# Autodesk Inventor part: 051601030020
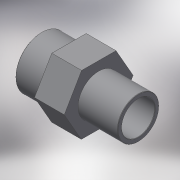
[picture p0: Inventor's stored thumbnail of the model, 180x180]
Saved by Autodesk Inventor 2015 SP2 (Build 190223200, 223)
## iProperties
Created: 2017-10
Part Number: 051601030020
Material: Generic
Description: PLASSON THR. REDUCING NIPPLE 3"-2" PVC
Document SubType Name: Modeling
Designer: KIM
Density: 1 g/cm^3
Appearance: Default
Author: KIM
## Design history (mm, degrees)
derived "051601.ipt"
feature "Solid1::051601.ipt"
tag "TaggingFeature1"
body "Solid1"
other parameters: "d0" = 83, "d13" = 0, "d14" = 0.59614, "d18" = 39.6, "d19" = 87.884, "d21" = 59.614, "d23" = 70.3072, "d24" = 47.6912, "d25" = 33, "R_1" = 59.614, "lt_" = 33, "H_" = 83, "R_" = 87.884
